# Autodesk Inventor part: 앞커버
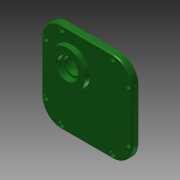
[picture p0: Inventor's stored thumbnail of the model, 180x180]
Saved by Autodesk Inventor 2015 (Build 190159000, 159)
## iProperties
Created: 2016-12
Part Number: 앞커버
Material: 알루미늄 6061
Document SubType Name: Modeling
Designer: mduedu
Density: 2.71 g/cm^3
Appearance: 매끄러움 - 짙은 산림 녹색
Mass: 518.945 g
Surface Area: 476.271 cm^2
Volume: 191.493 cm^3
Author: mduedu
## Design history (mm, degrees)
sketch "스케치1"
  geometry: L1 (-46, 42)-(-46, -36); L2 (-16, 72)-(62, 72); L3 (92, 42)-(92, -36); L4 (62, -66)-(-16, -66); A1 r 30 centre (-16, -36) between (-46, -36) and (-16, -66); A2 r 30 centre (62, 42) between (92, 42) and (62, 72); A3 r 30 centre (62, -36) between (62, -66) and (92, -36); A4 r 30 centre (-16, 42) between (-16, 72) and (-46, 42); 1 further point
  constraints: 8 end point, 8 point on circle, 8 tangent, 4 centre point, 3 equal radius, 2 perpendicular, 1 horizontal
  dimensions: "d89" = 30 radius of A2; "d90" = 92 distance from line of L3 point (0, 0); "d91" = 138 distance between parallel lines of L4 L2; "d92" = 72 distance from line of point (0, 0) L2; "d114" = 46 distance from line of point (0, 0) L1
extrude "돌출1" new body sketch "스케치1" distance "d3" = 10; taper "d4" = 0 deg
sketch "스케치2"
  geometry: C1 r 21 at (0, 26); 1 further point
  constraints: 1 centre point, 1 vertical alignment
  dimensions: "d5" = 42 diameter of C1; "d7" = 26 distance of C1.centre point (0, 0)
extrude "돌출2" join sketch "스케치2" distance "d8" = 7; taper "d9" = 0 deg
sketch "스케치3"
  geometry: C1 r 15 at (0, -28.87); C2 r 21 at (0, 26) reference; C3 r 15 at (-54.87, 26); 1 further point
  constraints: 2 centre point, 1 horizontal alignment, 1 vertical alignment
  dimensions: "d10" = 30 diameter of C1; "d71" = 54.87 distance of C1.centre C2.centre; "d94" = 30 diameter of C3; "d95" = 54.87 distance of C2.centre C3.centre
extrude "돌출3" join sketch "스케치3" distance "d12" = 7; taper "d13" = 0 deg; dims "d50" = 90 deg
sketch "스케치4"
  geometry: C1 r 21 at (0, 26) reference; C2 r 28 at (0, 26); 1 further point
  constraints: 1 centre point, 1 coincident
  dimensions: "d14" = 56 diameter of C2
extrude "돌출4" join sketch "스케치4" distance "d15" = 7; taper "d16" = -5 deg
hole "구멍1" diameter "d19" = 35; stored, may be unused: countersink angle "d23" = 90 deg, drill point angle "d25" = 0 deg; dims "d17" = 10, "d18" = 10, "d20" = 6, "d21" = 4, "d22" = 2, "d24" = 10
hole "구멍2" diameter "d28" = 22; stored, may be unused: countersink angle "d32" = 90 deg, drill point angle "d34" = 0 deg; dims "d26" = 10, "d27" = 10, "d29" = 6, "d30" = 4, "d31" = 2, "d33" = 7
hole "구멍8" diameter "d98" = 22; stored, may be unused: countersink angle "d102" = 90 deg, drill point angle "d104" = 0 deg; dims "d96" = 10, "d97" = 10, "d99" = 6, "d100" = 4, "d101" = 2, "d103" = 7
hole "구멍3" diameter "d37" = 19; stored, may be unused: countersink angle "d41" = 90 deg, drill point angle "d43" = 0 deg; dims "d35" = 10, "d36" = 10, "d38" = 6, "d39" = 4, "d40" = 2, "d42" = 1
hole "구멍9" diameter "d107" = 19; stored, may be unused: countersink angle "d111" = 90 deg, drill point angle "d113" = 0 deg; dims "d105" = 10, "d106" = 10, "d108" = 6, "d109" = 4, "d110" = 2, "d112" = 1
hole "구멍4" diameter "d46" = 32; stored, may be unused: countersink angle "d50" = 90 deg, drill point angle "d52" = 0 deg; dims "d44" = 10, "d45" = 10, "d47" = 6, "d48" = 4, "d49" = 2, "d51" = 8
hole "구멍5" diameter "d55" = 25; stored, may be unused: countersink angle "d59" = 90 deg, drill point angle "d61" = 0 deg; dims "d53" = 10, "d54" = 10, "d56" = 6, "d57" = 4, "d58" = 2, "d60" = 8
fillet "모깎기1" dims "d62" = 0.3
fillet "모깎기2" dims "d63" = 2
chamfer "모따기1" distance "d64" = 1; stored, may be unused: second distance "d65" = 2, angle "d66" = 45 deg
fillet "모깎기4" dims "d68" = 2
fillet "모깎기5" dims "d69" = 0.3
fillet "모깎기6" dims "d70" = 2
sketch "스케치5"
  geometry: L1 (62, 72)-(-16, 72) reference; L2 (92, -36)-(92, 42) reference; L3 (-16, -66)-(62, -66) reference; L4 (-46, 42)-(-46, -36) reference; L5 (-40, 42)-(-40, -36); L6 (-16, -60)-(62, -60); L7 (86, -36)-(86, 42); L8 (62, 66)-(-16, 66); A1 r 30 centre (62, 42) between (92, 42) and (62, 72) reference; A2 r 30 centre (62, -36) between (62, -66) and (92, -36) reference; A3 r 30 centre (-16, -36) between (-46, -36) and (-16, -66) reference; A4 r 30 centre (-16, 42) between (-16, 72) and (-46, 42) reference; A5 r 24 centre (-16, -36) between (-40, -36) and (-16, -60); A6 r 24 centre (62, -36) between (62, -60) and (86, -36); A7 r 24 centre (62, 42) between (86, 42) and (62, 66); A8 r 24 centre (-16, 42) between (-16, 66) and (-40, 42)
  constraints: 8 end point, 8 point on circle, 4 centre point, 7 other
  dimensions: "d93" = 6 distance between parallel lines of L5 L4
sketch "스케치7"
  geometry: L1 (62, 66)-(-16, 66) reference; L2 (86, -36)-(86, 42) reference; L3 (-16, -60)-(62, -60) reference; L4 (-40, 42)-(-40, -36) reference; A1 r 24 centre (62, 42) between (86, 42) and (62, 66) reference; A2 r 24 centre (62, -36) between (62, -60) and (86, -36) reference; A3 r 24 centre (-16, -36) between (-40, -36) and (-16, -60) reference; A4 r 24 centre (-16, 42) between (-16, 66) and (-40, 42) reference; 8 further points
  constraints: 8 coincident
hole "구멍7" sketch "스케치7" at (-40, 42), (-40, -36), (-16, -60), (62, -60), (86, -36), (86, 42), (62, 66), (-16, 66) diameter "d80" = 4.5; stored, may be unused: countersink angle "d84" = 90 deg, drill point angle "d86" = 0 deg; dims "d81" = 6, "d82" = 8, "d83" = 4.6, "d85" = 8
node "솔리드1"
